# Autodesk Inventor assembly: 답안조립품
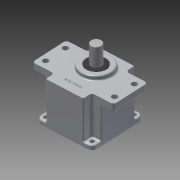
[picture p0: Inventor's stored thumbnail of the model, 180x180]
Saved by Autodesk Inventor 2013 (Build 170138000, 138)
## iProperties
Created: 2015-07
Part Number: 답안조립품
Document SubType Name: Assembly
Designer: user
Author: user
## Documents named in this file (12)
- C:\Users\user\Desktop\450734V1008\답안조립품.iam
- C:\Users\user\Desktop\450734V1008\메인축.ipt
- C:\Users\user\Desktop\450734V1008\베어링 6003.ipt
- 베어링 6003.ipt
- C:\Users\user\Desktop\450734V1008\베어링 608.ipt
- 베어링 608.ipt
- C:\Users\user\Desktop\450734V1008\서브축.ipt
- C:\Users\user\Desktop\450734V1008\본체.ipt
- C:\Users\user\Desktop\450734V1008\커버.ipt
- C:\Users\user\Desktop\450734V1008\오일실 8x22x7.ipt
- C:\Users\user\Desktop\450734V1008\오일실 17x32x8.ipt
- C:\Users\user\Desktop\450734V1008\M4x0.5x16.ipt
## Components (4 placed, 1 different names)
1. M4x0.5x12:1
2. M4x0.5x12:2
3. M4x0.5x12:3
4. M4x0.5x12:4
